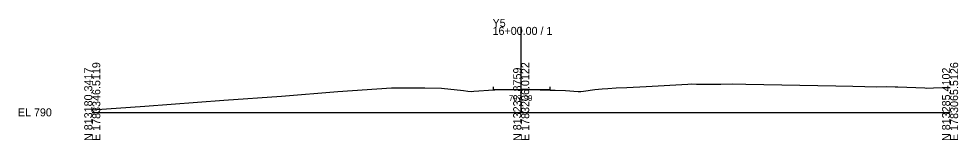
# Model space of a CAD drawing. Extents: x -26 to 1603, y -10 to 6526.
# Drawn here: x 1274.3 to 1602.8, y 2990.3 to 3032.6 of the extents above; entities that cross this region are included whole.
import ezdxf

# ---------------------------------------------------------------- set-up
doc = ezdxf.new("R2010")
doc.units = 0
for name, color, linetype in [('Exist Cross Section Cell', 7, 'Continuous'), ('Exist XS Center Line Elevation Label', 7, 'Continuous'), ('Exist XS Ground Line', 7, 'Continuous'), ('Prop XS EOT Tick Mark', 7, 'Continuous'), ('Prop XS Finish Grade Pavement', 7, 'Continuous')]:
    doc.layers.add(name, color=color, linetype=linetype)

msp = doc.modelspace()

# ---------------------------------------------------------------- linework, layer by layer
at = {"layer": 'Exist Cross Section Cell'}
for p, q in [((1450, 3000), (1450, 3029.79)), ((1300, 3000), (1450, 3000)), ((1450, 3000), (1600, 3000))]:
    msp.add_line(p, q, dxfattribs=at)
at = {"layer": 'Exist XS Ground Line'}
for p, q in [((1493.77, 3008.98), (1508.25, 3009.83)), ((1508.25, 3009.83), (1509.72, 3009.9)), ((1509.72, 3009.9), (1511.34, 3009.88)), ((1511.34, 3009.88), (1518.49, 3009.78)), ((1518.49, 3009.78), (1519.85, 3009.81)), ((1519.85, 3009.81), (1523.9, 3009.93)), ((1523.9, 3009.93), (1528.6, 3009.81)), ((1528.6, 3009.81), (1560.09, 3009.27)), ((1366.18, 3005.64), (1385.9, 3007.27)), ((1385.9, 3007.27), (1404.7, 3008.52)), ((1404.7, 3008.52), (1411.38, 3008.57)), ((1411.38, 3008.57), (1414.06, 3008.59)), ((1414.06, 3008.59), (1416.25, 3008.52)), ((1416.25, 3008.52), (1422.1, 3008.41)), ((1422.1, 3008.41), (1429.79, 3007.56)), ((1429.79, 3007.56), (1431.35, 3007.37)), ((1431.35, 3007.37), (1432.7, 3007.32)), ((1432.7, 3007.32), (1433.4, 3007.34)), ((1433.4, 3007.34), (1440.35, 3007.82)), ((1440.35, 3007.82), (1440.76, 3007.83)), ((1440.76, 3007.83), (1450.13, 3008)), ((1450.13, 3008), (1453.01, 3007.94)), ((1453.01, 3007.94), (1460.14, 3007.78)), ((1460.14, 3007.78), (1461.9, 3007.73)), ((1461.9, 3007.73), (1465.54, 3007.66)), ((1465.54, 3007.66), (1469.98, 3007.3)), ((1469.98, 3007.3), (1470.82, 3007.24)), ((1470.82, 3007.24), (1471.81, 3007.4)), ((1471.81, 3007.4), (1475.78, 3007.99)), ((1475.78, 3007.99), (1478.36, 3008.19)), ((1478.36, 3008.19), (1480.28, 3008.3)), ((1480.28, 3008.3), (1483.18, 3008.5)), ((1483.18, 3008.5), (1486.95, 3008.63)), ((1486.95, 3008.63), (1493.77, 3008.98)), ((1560.09, 3009.27), (1565.95, 3009.11)), ((1565.95, 3009.11), (1574.33, 3008.87)), ((1574.33, 3008.87), (1577.78, 3008.97)), ((1577.78, 3008.97), (1580.84, 3008.89)), ((1580.84, 3008.89), (1581.68, 3008.88)), ((1581.68, 3008.88), (1591.11, 3008.49)), ((1591.11, 3008.49), (1591.64, 3008.46)), ((1591.64, 3008.46), (1594.14, 3008.53)), ((1594.14, 3008.53), (1600, 3008.64)), ((1318.4, 3002.11), (1346.03, 3004.28)), ((1346.03, 3004.28), (1366.18, 3005.64)), ((1300, 3000.91), (1318.4, 3002.11))]:
    msp.add_line(p, q, dxfattribs=at)
at = {"layer": 'Prop XS EOT Tick Mark'}
for p, q in [((1440.35, 3007.95), (1440.35, 3008.95)), ((1460.14, 3007.91), (1460.14, 3008.91))]:
    msp.add_line(p, q, dxfattribs=at)
at = {"layer": 'Prop XS Finish Grade Pavement'}
for p, q in [((1440.35, 3007.95), (1440.76, 3007.96)), ((1440.76, 3007.96), (1450.13, 3008.12)), ((1450.13, 3008.12), (1453.01, 3008.06)), ((1453.01, 3008.06), (1460.14, 3007.91))]:
    msp.add_line(p, q, dxfattribs=at)

# ---------------------------------------------------------------- texts
at = {"layer": 'Exist Cross Section Cell'}
for s, p in [('Y5', (1440, 3029.79)), ('16+00.00 / 1', (1440, 3026.99)), ('EL 790', (1274, 2998.6))]:
    msp.add_text(s, height=2.8, dxfattribs=at).set_placement(p)
for s, p in [('E 1783346.5119', (1302.8, 2990)), ('E 1783206.0122', (1452.8, 2990)), ('E 1783065.5126', (1602.8, 2990)), ('N 813180.3417', (1300, 2990)), ('N 813232.8759', (1450, 2990)), ('N 813285.4102', (1600, 2990))]:
    msp.add_text(s, height=2.8, rotation=90, dxfattribs=at).set_placement(p)
at = {"layer": 'Exist XS Center Line Elevation Label'}
msp.add_text('797.99', height=2, dxfattribs=at).set_placement((1445.73, 3003.99))

doc.saveas('drawing.dxf')
